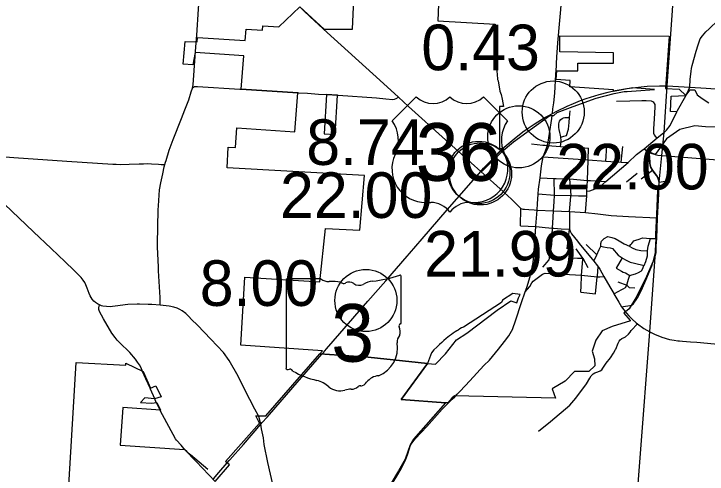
# Model space of a CAD drawing. Extents: x 1729596 to 1934326, y 644115 to 911751.
# Drawn here: x 1855413 to 1872161, y 810808 to 821917 of the extents above; entities that cross this region are included whole.
import ezdxf

# ---------------------------------------------------------------- set-up
doc = ezdxf.new("R2010")
doc.units = 0
for name, color, linetype in [('Default', 7, 'Continuous'), ('GM_X_City_Street', 7, 'Continuous'), ('GM_X_Corporation', 7, 'Continuous'), ('GM_X_County_Road', 7, 'Continuous'), ('GM_X_State_Route', 7, 'Continuous'), ('GM_X_State_Shield', 7, 'Continuous'), ('GM_X_Township', 7, 'Continuous'), ('GM_X_Township_Road', 7, 'Continuous'), ('GM_X_US_Route', 7, 'Continuous'), ('GM_X_US_Shield', 7, 'Continuous')]:
    doc.layers.add(name, color=color, linetype=linetype)

msp = doc.modelspace()

# ---------------------------------------------------------------- linework, layer by layer
at = {"layer": 'Default'}
for centre in [(1868443, 819548), (1867611, 818950), (1866645, 818090), (1866645, 818090), (1866685, 818054), (1863917, 814999)]:
    msp.add_circle(centre, 750, dxfattribs=at)
at = {"layer": 'GM_X_City_Street'}
for points in [[(1859794, 820906), (1859818, 821219)], [(1862296, 820012), (1862506, 819999)], [(1862770, 819982), (1862964, 819970), (1862980, 819969)], [(1871110, 819046), (1871124, 819057), (1871182, 819113), (1871265, 819220), (1871428, 819552), (1871447, 819585), (1871645, 819941), (1871647, 819944), (1871670, 819986), (1871678, 820004)], [(1863244, 819953), (1864174, 819889), (1864402, 819867), (1864570, 819853), (1864610, 819857), (1864649, 819871), (1864708, 819903)], [(1869969, 819812), (1870296, 819821), (1870580, 819825), (1870662, 819825)], [(1870662, 819825), (1870665, 819825), (1870686, 819825), (1870812, 819821), (1870858, 819797), (1870899, 819732), (1870898, 819669), (1870883, 819386), (1870863, 819146), (1870862, 819092), (1870864, 819034), (1870877, 818999), (1870902, 818968), (1870950, 818924)], [(1871428, 819552), (1871278, 819563), (1871294, 819932), (1871647, 819944)], [(1868627, 818944), (1868702, 818965), (1868767, 818983), (1868813, 819135), (1868824, 819291), (1868837, 819417), (1868848, 819578)], [(1868318, 818823), (1868408, 819390), (1868417, 819463)], [(1868619, 818717), (1868634, 818829), (1868636, 818865), (1868630, 818931), (1868627, 818944), (1868616, 818991), (1868603, 819050), (1868589, 819130), (1868581, 819174), (1868580, 819266), (1868596, 819326), (1868624, 819370), (1868657, 819390), (1868687, 819404), (1868723, 819412), (1868755, 819418), (1868837, 819417)], [(1870615, 818642), (1870639, 818661), (1870950, 818924), (1871110, 819046)], [(1868078, 817555), (1868079, 817572), (1868088, 817688), (1868126, 817958), (1868161, 818253), (1868200, 818465), (1868301, 818741), (1868308, 818760), (1868318, 818823)], [(1867916, 818779), (1868190, 818751), (1868191, 818751)], [(1868191, 818751), (1868250, 818745), (1868301, 818741), (1868619, 818717), (1868949, 818705), (1869292, 818679)], [(1868836, 817146), (1869223, 817120), (1869252, 817526), (1869257, 817637), (1869326, 817645), (1869394, 817673), (1869522, 817716), (1869565, 817745), (1869717, 817873), (1870254, 818326), (1870457, 818519), (1870615, 818642)], [(1869257, 817637), (1869264, 817763), (1869268, 817897), (1869284, 818388), (1869285, 818397), (1869292, 818679)], [(1869714, 818365), (1869739, 818731)], [(1870083, 818338), (1870123, 818713)], [(1870639, 818661), (1870705, 818615), (1870759, 818578), (1870769, 818573)], [(1868200, 818465), (1869285, 818397), (1869714, 818365), (1870083, 818338), (1870254, 818326)], [(1870569, 817936), (1870841, 818142)], [(1870211, 817860), (1870470, 818075)], [(1868126, 817958), (1868463, 817946), (1868499, 817944), (1868515, 817944)], [(1868465, 817382), (1868477, 817541), (1868463, 817946)], [(1868515, 817944), (1868765, 817935), (1868777, 817934)], [(1868777, 817934), (1868845, 817932), (1869268, 817897), (1869342, 817891), (1869717, 817873)], [(1868870, 817512), (1868872, 817530), (1868845, 817932)], [(1870997, 817576), (1871001, 817788)], [(1868056, 817177), (1868065, 817339), (1868078, 817555)], [(1868079, 817572), (1868477, 817541)], [(1868477, 817541), (1868865, 817530)], [(1868836, 817146), (1868870, 817512)], [(1868865, 817530), (1868872, 817530), (1869053, 817525), (1869252, 817526)], [(1868441, 817012), (1868448, 817163), (1868465, 817382)], [(1867651, 816799), (1867664, 817220)], [(1868026, 816789), (1868056, 817177)], [(1868420, 816588), (1868429, 816742), (1868441, 817012)], [(1869223, 817120), (1869523, 817094), (1869840, 817054), (1870261, 817024), (1870943, 816996), (1870961, 816995)], [(1867651, 816799), (1868026, 816783), (1868029, 816783)], [(1867945, 815848), (1867947, 815858), (1867966, 816000), (1868000, 816416), (1868012, 816665), (1868026, 816783), (1868026, 816789)], [(1868029, 816783), (1868245, 816761), (1868429, 816742), (1868459, 816741)], [(1868459, 816741), (1868634, 816731), (1868837, 816721)], [(1868776, 816244), (1868837, 816721)], [(1868193, 815800), (1868251, 815868), (1868290, 815913), (1868344, 815981), (1868375, 816154), (1868411, 816354), (1868414, 816482), (1868420, 816588)], [(1869420, 815948), (1869492, 816098), (1869556, 816230), (1869590, 816308), (1869593, 816374), (1869609, 816429), (1869672, 816496), (1869765, 816547)], [(1869765, 816547), (1869857, 816521), (1869939, 816498), (1870039, 816440), (1870157, 816365), (1870285, 816308), (1870295, 816304), (1870349, 816267), (1870437, 816233), (1870557, 816202), (1870723, 816195)], [(1869910, 815156), (1870029, 815227), (1870080, 815254), (1870132, 815283), (1870188, 815314), (1870220, 815371), (1870244, 815454), (1870259, 815510), (1870275, 815562), (1870297, 815598), (1870343, 815622), (1870428, 815646), (1870502, 815675), (1870578, 815717), (1870611, 815773), (1870633, 815841), (1870636, 815847), (1870680, 815941), (1870721, 816079), (1870723, 816195), (1870740, 816306), (1870790, 816499)], [(1870285, 816308), (1870321, 816354), (1870345, 816378), (1870368, 816410), (1870392, 816438), (1870436, 816453), (1870516, 816477), (1870596, 816514), (1870790, 816499), (1870933, 816495), (1870947, 816494)], [(1869492, 816098), (1869239, 816348)], [(1869590, 816308), (1869656, 816290), (1869745, 816281), (1869819, 816271), (1869874, 816255), (1870015, 816089), (1870104, 816030), (1870115, 816022), (1870205, 815976), (1870301, 815925), (1870403, 815896), (1870636, 815847)], [(1869157, 816021), (1869157, 816024), (1868996, 816244)], [(1868907, 816028), (1869031, 816023), (1869157, 816024), (1869282, 815797)], [(1869128, 815581), (1869129, 815613), (1869160, 815986), (1869157, 816021)], [(1870104, 816030), (1869966, 815778), (1870093, 815705), (1870133, 815683), (1870187, 815667), (1870297, 815598)], [(1867761, 815208), (1867805, 815310), (1867884, 815579), (1867924, 815749), (1867945, 815848)], [(1869509, 815593), (1869530, 815808)], [(1867761, 815208), (1867878, 815333), (1867925, 815423), (1867955, 815463), (1868186, 815638), (1868244, 815655), (1868405, 815651), (1869129, 815613), (1869506, 815569), (1869567, 815571), (1869669, 815577)], [(1869111, 815196), (1869119, 815352), (1869128, 815581)], [(1869464, 815163), (1869506, 815569), (1869509, 815593)], [(1870002, 815453), (1870220, 815371)], [(1870220, 815371), (1870280, 815316), (1870410, 815305)], [(1867464, 814315), (1867470, 814324), (1867530, 814508), (1867675, 814949), (1867761, 815208)], [(1869111, 815196), (1869464, 815163)], [(1866148, 812764), (1866195, 812814), (1866431, 813056), (1866765, 813427), (1866903, 813557), (1867120, 813823), (1867265, 814005), (1867368, 814147), (1867464, 814315)], [(1858816, 812624), (1858712, 812860)], [(1862504, 807234), (1862441, 807407), (1862377, 807590), (1862238, 807946), (1862134, 808217), (1862091, 808342), (1862056, 808446), (1862054, 808456), (1861975, 808879), (1861910, 809276), (1861885, 809449), (1861803, 809811), (1861778, 810016), (1861699, 810418), (1861546, 811089), (1861463, 811523), (1861444, 811686), (1861392, 811897), (1861379, 812013)]]:
    msp.add_lwpolyline(points, dxfattribs=at)
at = {"layer": 'GM_X_Corporation'}
for points in [[(1872369, 819183), (1872118, 819190), (1871863, 819214), (1871502, 819125), (1871177, 818898), (1870906, 818525), (1870848, 818543), (1870767, 818577), (1870760, 818526), (1870768, 818476), (1870779, 818314), (1870786, 818263), (1870803, 818212), (1870841, 818142), (1870892, 818081), (1870941, 818016), (1870984, 817932), (1871003, 817857), (1871186, 817888), (1871257, 817859), (1870965, 817659), (1870940, 817085), (1870914, 816591), (1870918, 816409), (1870920, 816216), (1870850, 815933), (1870694, 815581), (1870461, 815102), (1870281, 814797), (1870152, 814693), (1870300, 814517), (1870310, 814507), (1869865, 814374), (1869626, 814263), (1869472, 814042), (1869383, 813776), (1869438, 813593), (1869447, 813422), (1869302, 813286), (1868954, 813287), (1868735, 813050), (1868415, 812867), (1868495, 812643), (1866054, 812701), (1865997, 812642), (1865896, 812527), (1865843, 812531), (1864768, 812610), (1865403, 813477), (1863975, 813629), (1862805, 813710), (1862871, 813787), (1860894, 813922), (1860996, 815560), (1862803, 815449), (1862941, 816737), (1863769, 816697), (1863883, 818014), (1860562, 818202), (1860587, 818701), (1860771, 818691), (1860802, 819164), (1862199, 819069), (1862276, 820013), (1860906, 820099), (1860970, 820906), (1859791, 820983), (1859738, 820687), (1859505, 820707), (1859552, 821251), (1859841, 821244), (1859848, 821345), (1860999, 821277), (1861021, 821551), (1861422, 821527), (1861430, 821628), (1861816, 821605), (1862321, 822084), (1862912, 821546), (1863596, 821544), (1863668, 823164)], [(1865687, 822560), (1865651, 821750), (1867041, 821665), (1867085, 821260), (1867068, 821136), (1867065, 820962), (1867060, 820821), (1867068, 820747), (1867072, 820594), (1867087, 820460), (1867100, 820333), (1867115, 820300), (1867151, 820053), (1867187, 819974), (1867212, 819855), (1867245, 819678), (1867145, 819678), (1867148, 818668), (1867246, 818668), (1867161, 818594), (1866699, 818140), (1866722, 818118), (1867219, 818607), (1867231, 818617), (1867484, 818828), (1868360, 819462), (1868454, 819464), (1868541, 819536), (1868921, 819679), (1869480, 819883), (1869917, 819994), (1870158, 820041), (1870228, 820041), (1870333, 820049), (1870889, 820088), (1870356, 820135), (1869899, 820044), (1869899, 820085), (1868844, 820159), (1868852, 820309), (1868513, 820332), (1868528, 820542), (1869039, 820542), (1869039, 820726), (1869899, 820726), (1869899, 820974), (1868600, 820997), (1868600, 821384), (1871245, 821376), (1871152, 820118), (1871483, 820096), (1871642, 819946), (1871748, 820085), (1871861, 820081), (1871921, 819965), (1872043, 819876), (1872199, 819766)], [(1856704, 809881), (1856773, 811076), (1856914, 813505), (1858114, 813436), (1858118, 813482), (1858535, 813283), (1858712, 812884), (1858845, 812940), (1858970, 812675), (1858813, 812629), (1858574, 812648), (1858471, 812534), (1858741, 812523), (1858864, 812540), (1858957, 812354), (1858043, 812416), (1857978, 811505), (1859535, 811404), (1859815, 811112), (1860275, 810628), (1860621, 811028), (1860529, 811110), (1861344, 812036), (1861260, 812216), (1861498, 812216), (1862805, 813710), (1863975, 813629), (1865403, 813477), (1864768, 812610), (1865843, 812531), (1865065, 811655), (1864989, 811518), (1864863, 811170), (1864701, 810884), (1864525, 810591)]]:
    msp.add_lwpolyline(points, dxfattribs=at)
for points in [[(1862906, 819024), (1863171, 819007), (1863230, 819954), (1862964, 819970)], [(1865403, 813477), (1865595, 813463), (1865838, 813709), (1866105, 814049), (1866357, 814208), (1867086, 814766), (1867421, 814993), (1867566, 814942), (1867606, 815063), (1867642, 815146), (1867470, 815167), (1867221, 815005), (1867191, 814953), (1866273, 814357), (1866252, 814350), (1866224, 814337), (1866188, 814318), (1866148, 814284), (1866111, 814270), (1866070, 814243), (1866027, 814208), (1865989, 814179), (1865937, 814144), (1865899, 814117), (1865853, 814081), (1865802, 814037), (1865749, 813986), (1865694, 813935), (1865628, 813870), (1865561, 813807), (1865503, 813738)]]:
    msp.add_lwpolyline(points, close=True, dxfattribs=at)
at = {"layer": 'GM_X_County_Road'}
for points in [[(1871742, 820151), (1871742, 820151), (1871754, 820333), (1871771, 820532), (1871780, 820600), (1871796, 820672), (1871893, 821017), (1871942, 821170), (1871996, 821311), (1872051, 821390), (1872132, 821486), (1872206, 821558), (1872281, 821630), (1872352, 821694), (1872457, 821804), (1872502, 821861), (1872537, 821910), (1872571, 821965), (1872610, 822031), (1872673, 822132), (1872724, 822198)], [(1854991, 818481), (1855415, 818448), (1856692, 818365), (1857805, 818293), (1857887, 818287), (1857997, 818281), (1858195, 818286), (1858439, 818296), (1858547, 818299), (1858647, 818302), (1858736, 818299), (1858909, 818286), (1858969, 818282), (1859024, 818279), (1859060, 818281), (1859080, 818337), (1859095, 818374), (1859163, 818625), (1859262, 818885), (1859464, 819395), (1859545, 819601), (1859637, 819846), (1859697, 820038), (1859727, 820125), (1859753, 820151), (1859775, 820161), (1859787, 820164), (1859852, 820165), (1860873, 820101)], [(1871678, 820004), (1871742, 820151)], [(1860873, 820101), (1860906, 820099), (1862276, 820013), (1862296, 820012)], [(1862506, 819999), (1862509, 819999), (1862770, 819982)], [(1862980, 819969), (1863230, 819954), (1863244, 819953)], [(1871277, 818480), (1872206, 818406), (1875525, 818156), (1880663, 817814), (1881619, 818131), (1884362, 819111), (1887858, 818871), (1889457, 818761), (1891623, 818604), (1892346, 818560), (1895326, 818344), (1897532, 818224), (1897769, 818211), (1897801, 818204), (1897822, 818179)], [(1857182, 815299), (1857153, 815378), (1857124, 815436), (1857089, 815491), (1857039, 815553), (1856865, 815727), (1856650, 815933), (1856316, 816250), (1855886, 816655), (1854135, 818318), (1853948, 818496), (1853892, 818538)], [(1870769, 818573), (1870822, 818549), (1870854, 818540), (1870866, 818536)], [(1870866, 818536), (1870906, 818522), (1870968, 818509), (1871065, 818497), (1871277, 818480)], [(1858745, 814899), (1858660, 814905), (1858449, 814910), (1858391, 814909), (1858164, 814898), (1857861, 814864), (1857798, 814856), (1857739, 814849), (1857648, 814850), (1857559, 814865), (1857530, 814873), (1857479, 814893), (1857433, 814917), (1857388, 814948), (1857347, 814984), (1857307, 815028), (1857257, 815108), (1857229, 815169), (1857182, 815299)], [(1861324, 812212), (1861236, 812378), (1860992, 812846), (1860828, 813174), (1860617, 813548), (1860476, 813746), (1860173, 814063), (1859848, 814400), (1859708, 814543), (1859640, 814615), (1859568, 814682), (1859482, 814748), (1859421, 814784), (1859356, 814815), (1859277, 814840), (1859165, 814861), (1858949, 814884), (1858745, 814899)], [(1864113, 810086), (1864158, 810136), (1864387, 810382), (1864526, 810545), (1864640, 810718), (1864769, 810937), (1864875, 811146), (1864930, 811298), (1864995, 811506), (1865050, 811588), (1865117, 811671), (1865392, 811956), (1865763, 812377), (1866002, 812614)], [(1866002, 812614), (1866066, 812677), (1866122, 812737), (1866148, 812764)], [(1861379, 812013), (1861332, 812198), (1861324, 812212)]]:
    msp.add_lwpolyline(points, dxfattribs=at)
at = {"layer": 'GM_X_State_Route'}
for points in [[(1868532, 820875), (1868550, 821219), (1868792, 823921)], [(1868523, 820718), (1868532, 820875)], [(1868515, 820560), (1868520, 820663), (1868523, 820718)], [(1868423, 819513), (1868436, 819621), (1868455, 819771), (1868478, 820007), (1868509, 820452), (1868515, 820560)], [(1866346, 817716), (1866565, 817968), (1866588, 817993)], [(1866588, 817993), (1866693, 818111)], [(1866693, 818111), (1867234, 817626), (1867256, 817606)], [(1864967, 816131), (1865275, 816485), (1865884, 817183), (1866346, 817716)], [(1867256, 817606), (1867435, 817444), (1867478, 817401)], [(1867478, 817401), (1867625, 817254), (1867664, 817220), (1867706, 817207), (1867748, 817201), (1867855, 817194)], [(1867855, 817194), (1867983, 817185), (1868056, 817177)], [(1868056, 817177), (1868448, 817163), (1868836, 817146)], [(1868836, 817146), (1868837, 816776)], [(1868837, 816776), (1868837, 816721), (1868851, 816673), (1868887, 816606), (1869030, 816427), (1869071, 816377)], [(1869071, 816377), (1869420, 815948), (1869509, 815839), (1869530, 815808), (1869534, 815802)], [(1862967, 813834), (1863287, 814202), (1863966, 814984), (1864395, 815476), (1864911, 816067), (1864967, 816131)], [(1869534, 815802), (1869567, 815752), (1869669, 815577), (1869812, 815327), (1869906, 815164)], [(1869906, 815164), (1869910, 815156), (1870025, 814958), (1870094, 814847), (1870207, 814697)], [(1870207, 814697), (1870211, 814693), (1870271, 814626), (1870352, 814549), (1870443, 814463), (1870476, 814436), (1870628, 814325), (1870779, 814239), (1870889, 814182), (1871068, 814112), (1871253, 814061), (1871361, 814039), (1871455, 814026)], [(1871455, 814026), (1871491, 814021), (1871569, 814014), (1871759, 814000), (1871910, 813989), (1872340, 813955), (1872527, 813939), (1873053, 813896), (1874044, 813812), (1874182, 813797), (1874274, 813782), (1874381, 813759), (1874562, 813699), (1874700, 813634), (1874793, 813581), (1874892, 813523), (1878383, 811338), (1880549, 810005), (1880810, 809846), (1880939, 809769), (1881144, 809643), (1882507, 808811), (1883124, 808426)], [(1862898, 813755), (1862922, 813783), (1862967, 813834)], [(1861588, 812249), (1862256, 813018), (1862855, 813706), (1862898, 813755)], [(1861414, 812052), (1861532, 812184), (1861588, 812249)], [(1860617, 811135), (1860632, 811151), (1860959, 811525), (1861379, 812013), (1861414, 812052)], [(1860234, 810698), (1860366, 810850), (1860563, 811079), (1860617, 811135)]]:
    msp.add_lwpolyline(points, dxfattribs=at)
at = {"layer": 'GM_X_State_Shield'}
for p, q in [((1861987, 815485), (1861987, 813372)), ((1861987, 815485), (1861987, 813372)), ((1862830, 815522), (1862014, 815522)), ((1862830, 815522), (1862014, 815522)), ((1864771, 814469), (1864771, 815574)), ((1864771, 814469), (1864771, 815574)), ((1864771, 814469), (1864771, 814469)), ((1864771, 814469), (1864771, 814469))]:
    msp.add_line(p, q, dxfattribs=at)
for centre, radius, start, end in [((1862019, 815490), 32.3, 98.1301, 188.1301), ((1862019, 815490), 32.3, 98.1301, 188.1301), ((1863024, 815767), 313, 231.6195, 271.1119), ((1863024, 815767), 313, 231.6195, 271.1119), ((1863128, 814335), 1123, 80.4867, 94.9883), ((1863128, 814335), 1123, 80.4867, 94.9883), ((1864156, 814876), 594, 97.3462, 120.7689), ((1864156, 814876), 594, 97.3462, 120.7689), ((1863779, 818403), 2953, 275.8445, 288.9065), ((1863779, 818403), 2953, 275.8445, 288.9065), ((1864740, 815579), 31, 351.8621, 97.738), ((1864740, 815579), 31, 351.8621, 97.738), ((1863383, 815501), 90.3, 219.7921, 297.1024), ((1863383, 815501), 90.3, 219.7921, 297.1024), ((1863515, 815257), 188, 54.4667, 119.1411), ((1863515, 815257), 188, 54.4667, 119.1411), ((1863757, 815592), 226, 233.8562, 294.8282), ((1863757, 815592), 226, 233.8562, 294.8282), ((1864738, 814464), 33.2, 289.6038, 7.7341), ((1864738, 814464), 33.2, 289.6038, 7.7341), ((1864764, 814388), 48, 107.944, 210.337), ((1864764, 814388), 48, 107.944, 210.337), ((1864459, 814248), 288, 340.033, 23.6496), ((1864459, 814248), 288, 340.033, 23.6496), ((1864882, 814006), 210, 136.8065, 186.9296), ((1864882, 814006), 210, 136.8065, 186.9296), ((1863945, 813865), 739, 292.3089, 8.9858), ((1863945, 813865), 739, 292.3089, 8.9858), ((1862019, 813368), 32.5, 171.9584, 258.3066), ((1862019, 813368), 32.5, 171.9584, 258.3066), ((1862024, 813584), 248, 267.339, 280.6039), ((1862024, 813584), 248, 267.339, 280.6039), ((1862075, 813250), 89.5, 29.7484, 93.2717), ((1862075, 813250), 89.5, 29.7484, 93.2717), ((1863205, 815149), 2132, 240.4129, 257.1985), ((1863205, 815149), 2132, 240.4129, 257.1985), ((1864256, 812779), 404, 94.4031, 142.5768), ((1864256, 812779), 404, 94.4031, 142.5768), ((1862570, 812423), 667, 47.1842, 75.836), ((1862570, 812423), 667, 47.1842, 75.836), ((1863771, 812877), 63.5, 65.7517, 132.6484), ((1863771, 812877), 63.5, 65.7517, 132.6484), ((1863744, 813167), 239, 282.8732, 323.2771), ((1863744, 813167), 239, 282.8732, 323.2771), ((1863291, 813240), 423, 230.7004, 286.2918), ((1863291, 813240), 423, 230.7004, 286.2918), ((1863536, 812509), 348, 85.6951, 111.2099), ((1863536, 812509), 348, 85.6951, 111.2099), ((1863567, 813081), 226, 268.777, 315.5493), ((1863567, 813081), 226, 268.777, 315.5493)]:
    msp.add_arc(centre, radius, start, end, dxfattribs=at)
at = {"layer": 'GM_X_Township'}
msp.add_lwpolyline([(1870008, 803514), (1870309, 808163), (1870779, 814239), (1870903, 816053), (1870933, 816495), (1870943, 816996), (1871003, 817857), (1871065, 818497), (1871124, 819057), (1871199, 820179), (1871965, 831096), (1873866, 830983), (1874715, 830911), (1874782, 830900), (1876113, 830808), (1881808, 830417), (1885186, 830186), (1888609, 830001), (1895732, 829600), (1898513, 829466)], dxfattribs=at)
at = {"layer": 'GM_X_Township_Road'}
for points in [[(1859818, 821219), (1859833, 821406), (1859916, 822663), (1859971, 823438), (1859983, 823596), (1859988, 823723)], [(1859727, 820125), (1859741, 820205), (1859793, 820898), (1859794, 820906)], [(1871001, 817788), (1871003, 817857), (1870979, 817935), (1870937, 818014), (1870874, 818099), (1870841, 818142), (1870803, 818212), (1870786, 818263), (1870779, 818314), (1870768, 818476), (1870760, 818526), (1870759, 818578)], [(1858949, 814884), (1858944, 815073), (1858908, 815711), (1858905, 815815), (1858883, 816289), (1858879, 816365), (1858902, 817190), (1858907, 817282), (1858933, 817671), (1858963, 817835), (1859010, 818058), (1859043, 818222), (1859060, 818281)], [(1870844, 815892), (1870875, 815973), (1870903, 816053), (1870926, 816150), (1870932, 816316), (1870947, 816494), (1870961, 816995), (1870997, 817562), (1870997, 817576)], [(1870094, 814847), (1870189, 814864), (1870245, 814871), (1870293, 814877), (1870336, 814889), (1870372, 814914), (1870477, 815061), (1870573, 815247), (1870701, 815548), (1870821, 815832), (1870844, 815892)], [(1858524, 813285), (1858523, 813288), (1858486, 813376), (1858444, 813445), (1858400, 813513), (1858350, 813585), (1858214, 813747), (1857968, 813983), (1857911, 814041), (1857857, 814102), (1857782, 814210), (1857579, 814557), (1857484, 814732), (1857467, 814783), (1857464, 814822), (1857479, 814893)], [(1868090, 811845), (1868376, 812080), (1868841, 812471), (1868988, 812641), (1869243, 812986), (1869324, 813120), (1869362, 813182), (1869404, 813226), (1869447, 813255), (1869519, 813280), (1869574, 813300), (1869613, 813329), (1869643, 813365), (1869725, 813483), (1869823, 813611), (1869897, 813730), (1869945, 813815), (1869952, 813827), (1870008, 813965), (1870034, 814019), (1870058, 814049), (1870103, 814080), (1870160, 814108), (1870188, 814122), (1870258, 814187), (1870300, 814238), (1870327, 814273), (1870476, 814436)], [(1858712, 812860), (1858703, 812880), (1858602, 813109), (1858524, 813285)], [(1858858, 812530), (1858854, 812539), (1858816, 812624)], [(1858951, 812345), (1858946, 812355), (1858888, 812469), (1858858, 812530)], [(1859516, 811426), (1859452, 811506), (1859339, 811630), (1859319, 811662), (1858951, 812345)], [(1859590, 811355), (1859535, 811404), (1859516, 811426)], [(1860099, 810917), (1859678, 811276), (1859590, 811355)]]:
    msp.add_lwpolyline(points, dxfattribs=at)
at = {"layer": 'GM_X_US_Route'}
for points in [[(1862359, 822043), (1862416, 821990), (1862570, 821847), (1862984, 821471)], [(1871153, 820180), (1871199, 820179), (1871742, 820151), (1872137, 820124), (1875367, 819897), (1876072, 819853), (1876232, 819852), (1876406, 819857), (1876545, 819867), (1876727, 819890), (1876899, 819917), (1877009, 819941), (1877209, 819989), (1877624, 820113), (1878554, 820394), (1880687, 821035), (1883192, 821790)], [(1862984, 821471), (1864255, 820317), (1864708, 819903), (1864947, 819685), (1865843, 818874), (1866225, 818531)], [(1869772, 820024), (1869935, 820064), (1870218, 820115), (1870358, 820133), (1870708, 820169), (1871013, 820182), (1871153, 820180)], [(1868423, 819513), (1868530, 819569), (1868780, 819692), (1868932, 819756), (1869103, 819824), (1869240, 819873), (1869556, 819971), (1869772, 820024)], [(1867232, 818676), (1867261, 818703), (1867495, 818904), (1867708, 819068), (1867816, 819145), (1867983, 819256), (1868226, 819404), (1868324, 819459), (1868423, 819513)], [(1867046, 818494), (1867142, 818593), (1867232, 818676)], [(1866225, 818531), (1866693, 818111)], [(1866761, 818189), (1866781, 818212), (1866860, 818300), (1867046, 818494)], [(1866693, 818111), (1866761, 818189)]]:
    msp.add_lwpolyline(points, dxfattribs=at)
at = {"layer": 'GM_X_US_Shield'}
for p, q in [((1865135, 819917), (1864555, 819337)), ((1865135, 819917), (1864555, 819337)), ((1867339, 819337), (1866759, 819917)), ((1867339, 819337), (1866759, 819917)), ((1865367, 817365), (1865483, 817365)), ((1865367, 817365), (1865483, 817365)), ((1866411, 817365), (1866527, 817365)), ((1866411, 817365), (1866527, 817365))]:
    msp.add_line(p, q, dxfattribs=at)
for centre, radius, start, end in [((1865541, 820331), 580, 225.573, 314.427), ((1865541, 820331), 580, 225.573, 314.427), ((1866353, 820331), 580, 225.573, 314.427), ((1866353, 820331), 580, 225.573, 314.427), ((1863890, 818871), 812, 334.5471, 35.0009), ((1863890, 818871), 812, 334.5471, 35.0009), ((1868004, 818871), 812, 144.9991, 205.4529), ((1868004, 818871), 812, 144.9991, 205.4529), ((1865358, 818177), 812, 154.8319, 270.6383), ((1865358, 818177), 812, 154.8319, 270.6383), ((1866536, 818177), 812, 269.3617, 25.1681), ((1866536, 818177), 812, 269.3617, 25.1681), ((1865483, 816784), 580, 36.8699, 90), ((1865483, 816784), 580, 36.8699, 90), ((1866411, 816784), 580, 90, 143.1301), ((1866411, 816784), 580, 90, 143.1301)]:
    msp.add_arc(centre, radius, start, end, dxfattribs=at)

# ---------------------------------------------------------------- texts
at = {"layer": 'Default'}
for s, p in [('0.43', (1865257, 820557)), ('8.74', (1862476, 818270)), ('22.00', (1868516, 817679)), ('22.00', (1861842, 816992)), ('21.99', (1865324, 815577)), ('8.00', (1859903, 814868))]:
    msp.add_text(s, height=1100, dxfattribs=at).set_placement(p)
at = {"layer": 'GM_X_State_Shield'}
msp.add_text('3', height=1392, dxfattribs=at).set_placement((1863079, 813521))
msp.add_text('3', height=1392, dxfattribs=at).set_placement((1863079, 813521))
at = {"layer": 'GM_X_US_Shield'}
msp.add_text('36', height=1392.2, dxfattribs=at).set_placement((1865120, 817887))
msp.add_text('36', height=1392.2, dxfattribs=at).set_placement((1865120, 817887))

doc.saveas('drawing.dxf')
